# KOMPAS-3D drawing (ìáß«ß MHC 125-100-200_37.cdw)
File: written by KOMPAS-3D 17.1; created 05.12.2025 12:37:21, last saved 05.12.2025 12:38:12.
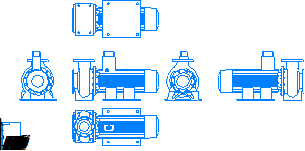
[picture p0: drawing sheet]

Sheet 1: A4, portrait

Title block, sheet 1: name: Насос MHC 125-100-200_37 / 37,0 кВт 3х380В; material: Сталь 10  ГОСТ 1050-88; mass: 326,62; sheets: 1; sheet format: A4

Views: Проекционный вид 2, Проекционный вид 3, Проекционный вид 4, Проекционный вид 5, Проекционный вид 6
Referenced files in \\adlc.lan\data\АДЛ_ПКД\3D-модели\ADL production\Насосы ГРАНПАМП\Насосы ГРАНПАМП серии МНС\KOMPAS 3D\: Насос MHC 125-100-200_37.m3d
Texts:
  Andrey
  АДЛ
Dimensions and other numbers on the sheet: 1:1; 1; 37,0 кВт 3х380В; 326,62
